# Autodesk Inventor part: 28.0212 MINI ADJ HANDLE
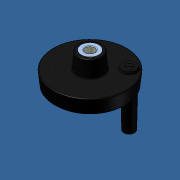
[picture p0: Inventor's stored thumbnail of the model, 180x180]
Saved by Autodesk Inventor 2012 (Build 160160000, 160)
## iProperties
Created: 2011-09
Part Number: 28.0212 MINI ADJ HANDLE
Document SubType Name: Modeling
Designer: Administrator
Density: 1 g/cm^3
Mass: 82.7447 g
Surface Area: 201.549 cm^2
Volume: 82.7447 cm^3
Material: Default
Author: Administrator
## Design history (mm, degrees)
feature "Base1"
workplane "Work Plane2"
  workplane "Work Plane1"
  workaxis "Work Axis1"
sketch "Sketch1"
  geometry: L1 (-6.71, 9.5)-(-6.71, -9.5) reference; 4 further points
  constraints: 2 horizontal alignment, 1 midpoint
  dimensions: "d9" = 8 distance from line of point (1.29, 0) L1
hole "Hole1" sketch "Sketch1" at (1.29, 0) diameter "d2" = 3.242; stored, may be unused: countersink angle "d6" = 90 deg, drill point angle "d8" = 118 deg; dims "d3" = 6, "d4" = 4, "d5" = 2, "d7" = 8
body "Solid1"
other parameters: "d0" = 90 deg
